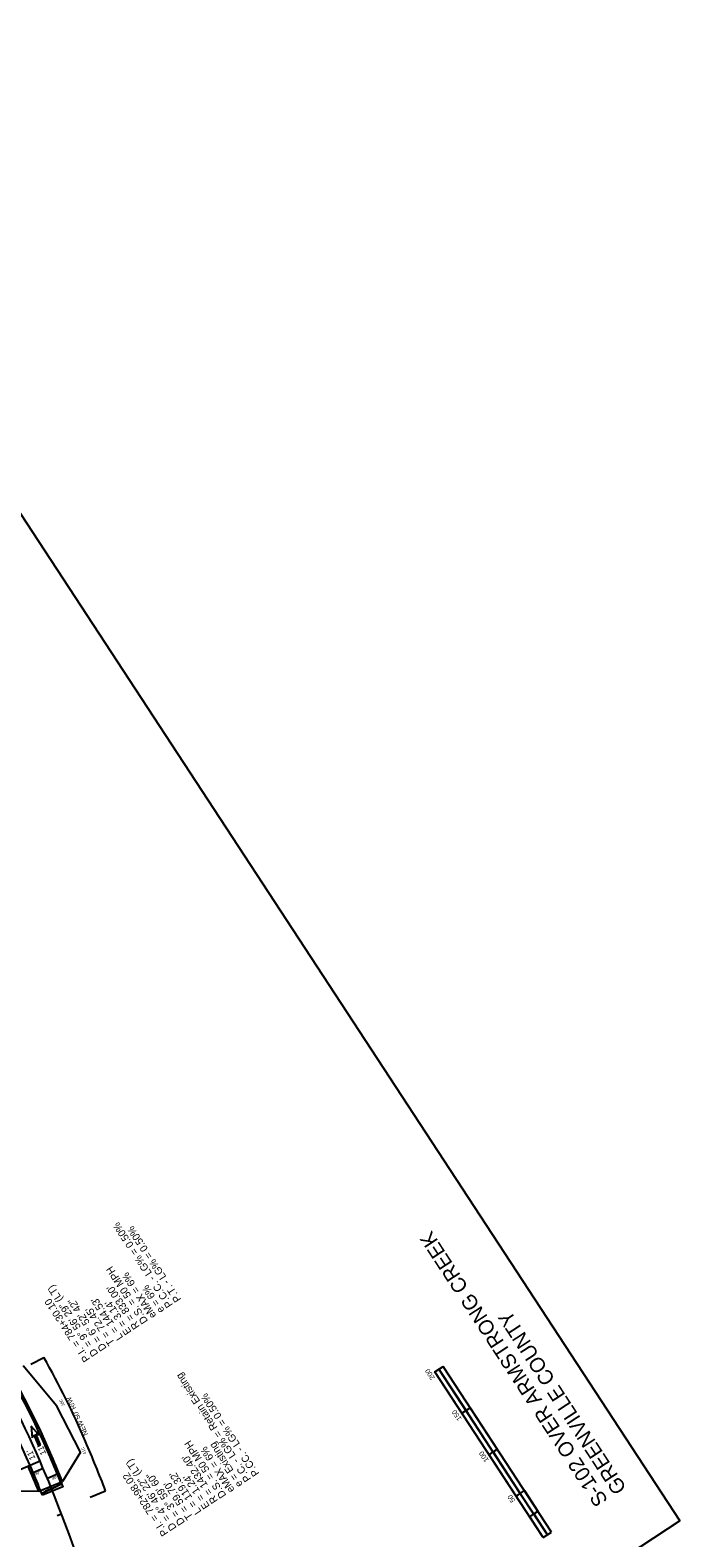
# Model space of a CAD drawing. Extents: x 1551641 to 1624343, y 1119533 to 1136600.
# Drawn here: x 1552891 to 1553547, y 1133795 to 1135318 of the extents above; entities that cross this region are included whole.
import ezdxf

# ---------------------------------------------------------------- set-up
doc = ezdxf.new("R2010")
doc.units = 0
for name, color, linetype in [('Prop CMT Pvmt Surface', 7, 'Continuous'), ('Prop CMT Pvmt Wedge Surface 1', 7, 'Continuous'), ('RD_HC_Cl', 7, 'Continuous'), ('RD_HC_Data', 7, 'Continuous'), ('RD_HC_Data_Tic', 7, 'Continuous'), ('RD_Sketch1', 7, 'Continuous'), ('RD_TX_Pipe_ElevEX', 7, 'Continuous'), ('RD_XS_EarthShd', 7, 'Continuous'), ('RD_XS_Pave', 7, 'Continuous'), ('RD_XS_PaveOvlay', 7, 'Continuous'), ('RD_XS_TX_Elev_EX', 7, 'Continuous'), ('RD_XS_TX_Slope', 7, 'Continuous'), ('Scratch_Level_0', 7, 'Continuous'), ('Scratch_Level_1', 7, 'Continuous')]:
    doc.layers.add(name, color=color, linetype=linetype)

msp = doc.modelspace()

# ---------------------------------------------------------------- linework, layer by layer
at = {"layer": 'Prop CMT Pvmt Surface'}
for p, q in [((1552893.7, 1133861.2), (1552903.8, 1133865.5)), ((1552908.1, 1133855.4), (1552918.2, 1133859.6))]:
    msp.add_line(p, q, dxfattribs=at)
at = {"layer": 'Prop CMT Pvmt Wedge Surface 1'}
for p, q in [((1552560.8, 1135318), (1553547.3, 1133812.4)), ((1553547.3, 1133812.4), (1552627.2, 1133209.5))]:
    msp.add_line(p, q, dxfattribs=at)
at = {"layer": 'RD_HC_Cl'}
msp.add_arc((1551585.1, 1133306.1), 1432.4, 18.5195, 23.2924, dxfattribs=at)
at = {"layer": 'RD_HC_Data'}
msp.add_line((1552900.8, 1133872.5), (1552777.1, 1133819.3), dxfattribs=at)
at = {"layer": 'RD_HC_Data_Tic'}
msp.add_line((1552922.5, 1133819.1), (1552917.9, 1133817.4), dxfattribs=at)
at = {"layer": 'RD_Sketch1'}
for p, q in [((1552921.7, 1133851.2), (1552923.5, 1133851.9)), ((1552899.4, 1133842.1), (1552901.3, 1133842.9))]:
    msp.add_line(p, q, dxfattribs=at)
for centre, radius, start, end in [((1552135.7, 1133543.2), 846, 23.2924, 33.2337), ((1551585.1, 1133306.1), 1419.4, 22.1864, 23.2924), ((1551585.1, 1133306.1), 1445.4, 22.1864, 23.2924)]:
    msp.add_arc(centre, radius, start, end, dxfattribs=at)
at = {"layer": 'RD_TX_Pipe_ElevEX'}
for q in [(1552922.4, 1133849.5), (1552902.5, 1133839.9)]:
    msp.add_line((1552912.4, 1133844.8), q, dxfattribs=at)
msp.add_lwpolyline([(1552903.2, 1133838.3), (1552901.3, 1133842.9), (1552921.7, 1133851.2), (1552923.6, 1133846.6)], close=True, dxfattribs=at)
msp.add_lwpolyline([(1552902.5, 1133839.9), (1552908.9, 1133843.1), (1552911.7, 1133844.4), (1552918.4, 1133847.7), (1552921, 1133848.9), (1552921.4, 1133849.1), (1552922.4, 1133849.5)], dxfattribs=at)
at = {"layer": 'RD_XS_EarthShd'}
msp.add_line((1552901.3, 1133842.9), (1552921.7, 1133851.2), dxfattribs=at)
for centre, radius, start, end in [((1552135.7, 1133543.2), 844, 23.2924, 33.2337), ((1552135.7, 1133543.2), 822, 23.2924, 33.2337), ((1551585.1, 1133306.1), 1421.4, 22.1864, 23.2924), ((1551585.1, 1133306.1), 1443.4, 22.1864, 23.2924)]:
    msp.add_arc(centre, radius, start, end, dxfattribs=at)
at = {"layer": 'RD_XS_Pave'}
for p, q in [((1552891.3, 1133970.5), (1552904.6, 1133977.3)), ((1552951.3, 1133836.3), (1552967, 1133842.7))]:
    msp.add_line(p, q, dxfattribs=at)
for centre, radius, start, end in [((1552135.7, 1133543.2), 883, 23.2924, 29.4522), ((1551585.1, 1133306.1), 1482.4, 21.2201, 23.2924)]:
    msp.add_arc(centre, radius, start, end, dxfattribs=at)
at = {"layer": 'RD_XS_PaveOvlay'}
for p, q in [((1552899.6, 1133899.1), (1552891.8, 1133908)), ((1552891.8, 1133908), (1552892.8, 1133896.2)), ((1552892.8, 1133896.2), (1552894.3, 1133899.1)), ((1552894.3, 1133899.1), (1552899.1, 1133888.1)), ((1552901.1, 1133889), (1552896.4, 1133900)), ((1552896.4, 1133900), (1552899.6, 1133899.1)), ((1552899.1, 1133888.1), (1552901.1, 1133889))]:
    msp.add_line(p, q, dxfattribs=at)
at = {"layer": 'RD_XS_TX_Elev_EX'}
for p, q in [((1552917.6, 1133928), (1552883.6, 1133968.8)), ((1552941.6, 1133881.6), (1552917.6, 1133928)), ((1552941.6, 1133881.6), (1552923.5, 1133851.9)), ((1552851, 1133843.1), (1552899.4, 1133842.1))]:
    msp.add_line(p, q, dxfattribs=at)
at = {"layer": 'Scratch_Level_0'}
msp.add_arc((1552135.7, 1133543.2), 833, 23.2924, 33.2337, dxfattribs=at)
at = {"layer": 'Scratch_Level_1'}
for p, q in [((1553299.6, 1133962.7), (1553308, 1133968.2)), ((1553409.2, 1133795.5), (1553299.6, 1133962.7)), ((1553386, 1133840), (1553303.8, 1133965.4)), ((1553304.6, 1133966), (1553304.6, 1133966)), ((1553305.5, 1133966.5), (1553305.5, 1133966.5)), ((1553306.3, 1133967.1), (1553306.3, 1133967.1)), ((1553307.1, 1133967.6), (1553307.1, 1133967.6)), ((1553417.6, 1133801), (1553308, 1133968.2)), ((1553327, 1133920.9), (1553335.4, 1133926.4)), ((1553335.4, 1133926.4), (1553335.4, 1133926.4)), ((1553354.4, 1133879.1), (1553362.8, 1133884.6)), ((1553381.8, 1133837.3), (1553390.2, 1133842.8)), ((1553413.4, 1133798.2), (1553386, 1133840)), ((1553390.2, 1133842.8), (1553390.2, 1133842.8)), ((1553395.5, 1133816.4), (1553403.9, 1133821.9)), ((1553409.2, 1133795.5), (1553417.6, 1133801))]:
    msp.add_line(p, q, dxfattribs=at)
for points in [[(1553327, 1133920.9), (1553299.6, 1133962.7), (1553303.8, 1133965.4), (1553331.2, 1133923.6)], [(1553358.6, 1133881.8), (1553331.2, 1133923.6), (1553335.4, 1133926.4), (1553362.8, 1133884.6)], [(1553381.8, 1133837.3), (1553354.4, 1133879.1), (1553358.5, 1133881.9), (1553386, 1133840)], [(1553399.7, 1133819.1), (1553386, 1133840), (1553390.2, 1133842.8), (1553403.9, 1133821.9)], [(1553409.2, 1133795.5), (1553395.5, 1133816.4), (1553399.8, 1133819.2), (1553413.5, 1133798.3)]]:
    msp.add_lwpolyline(points, close=True, dxfattribs=at)

# ---------------------------------------------------------------- texts
at = {"layer": 'Prop CMT Pvmt Surface'}
for s, p in [('-06', (1552900.3, 1133863.2)), ('+06', (1552918.6, 1133859.1))]:
    msp.add_text(s, height=3, rotation=202.9864, dxfattribs=at).set_placement(p)
at = {"layer": 'RD_HC_Data'}
for s, p in [('P.C.C. - LG% = 0.50%', (1553035.2, 1134030.5)), ('P.T. - LG% = 0.50%', (1553043.6, 1134036)), ('D.S. = 50 MPH', (1553010.1, 1134014.1)), ('eMAX = 6%', (1553018.5, 1134019.6)), ('    = 9%%d 56\' 29" (LT)', (1552959.9, 1133981.2)), ("R = 833.00'", (1553001.7, 1134008.6)), ('e = 6%', (1553026.8, 1134025)), ('P.I. = 784+30.10', (1552951.6, 1133975.7)), ('D = 6%%d 52\' 42"', (1552968.3, 1133986.7)), ("L = 144.53'", (1552985, 1133997.6)), ("E = 3.14'", (1552993.4, 1134003.1)), ("T = 72.45'", (1552976.6, 1133992.2)), ('D', (1552959.9, 1133981.2)), ('P.C. - LG% = Retain Existing', (1553114.3, 1133854.6)), ('P.CC. - LG% = 0.50%', (1553122.6, 1133860.1)), ('D.S. = 50 MPH', (1553089.2, 1133838.1)), ('eMAX = 6%', (1553097.6, 1133843.6)), ('e = Existing', (1553105.9, 1133849.1)), ('    = 4%%d 46\' 22" (LT)', (1553039, 1133805.3)), ("R = 1432.40'", (1553080.8, 1133832.7)), ('P.I. = 782+98.02', (1553030.6, 1133799.8)), ('D = 3%%d 59\' 60"', (1553047.4, 1133810.7)), ("T = 59.70'", (1553055.7, 1133816.2)), ("L = 119.32'", (1553064.1, 1133821.7)), ("E = 1.24'", (1553072.5, 1133827.2)), ('D', (1553039, 1133805.3))]:
    msp.add_text(s, height=7.5, rotation=123.2337, dxfattribs=at).set_placement(p)
at = {"layer": 'RD_TX_Pipe_ElevEX'}
for s, p in [('+5.5909', (1552913.9, 1133846.1)), ('-6.8909', (1552903.7, 1133841.4))]:
    msp.add_text(s, height=1.5, rotation=22.1864, dxfattribs=at).set_placement(p)
at = {"layer": 'RD_XS_Pave'}
msp.add_text("NEW 50' R/W", height=5, rotation=114.983, dxfattribs=at).set_placement((1552949.4, 1133899.7))
at = {"layer": 'RD_XS_PaveOvlay'}
for p in [(1552896.2, 1133875.3), (1552907.1, 1133880.2)]:
    msp.add_text("11'", height=6, rotation=113.1378, dxfattribs=at).set_placement(p)
at = {"layer": 'RD_XS_TX_Slope'}
for s, rotation, p in [('38C', 116.2053, (1552925.8, 1133929)), ('41C', 112.9864, (1552947.7, 1133880.2))]:
    msp.add_text(s, height=3, rotation=rotation, dxfattribs=at).set_placement(p)
at = {"layer": 'Scratch_Level_1'}
for s, height, rotation, p in [('S-102 OVER ARMSTRONG CREEK', 15, 123.2337, (1553475.1, 1133832.9)), ('GREENVILLE COUNTY', 15, 123.2337, (1553493.9, 1133845.2)), ('200', 5, 123.233, (1553299.9, 1133956.8)), ('150', 5, 123.2298, (1553327, 1133915.4)), ('100', 5, 123.2311, (1553354.4, 1133873.6)), ('50', 5, 123.2337, (1553381.1, 1133832.8))]:
    msp.add_text(s, height=height, rotation=rotation, dxfattribs=at).set_placement(p)

doc.saveas('drawing.dxf')
